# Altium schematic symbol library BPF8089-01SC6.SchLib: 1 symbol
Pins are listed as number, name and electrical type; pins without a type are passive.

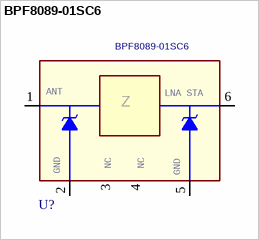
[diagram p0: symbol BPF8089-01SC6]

## BPF8089-01SC6
designator U?
footprint ST_SOT23-6L
pins: 1 ANT, 2 GND, 3 NC, 4 NC2, 5 GND2, 6 LNA_STA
